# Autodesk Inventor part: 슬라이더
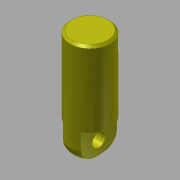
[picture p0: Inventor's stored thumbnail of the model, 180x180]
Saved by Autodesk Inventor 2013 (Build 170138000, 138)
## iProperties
Created: 2016-08
Part Number: 슬라이더
Material: 강철, 탄소
Document SubType Name: Modeling
Designer: mduedu
Density: 7.87 g/cm^3
Author: mduedu
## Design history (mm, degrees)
sketch "스케치1"
  geometry: C1 r 9 at (0, 0); 1 further point
  constraints: 1 centre point, 1 coincident
  dimensions: "d0" = 18 diameter of C1
extrude "돌출1" new body sketch "스케치1" distance "d1" = 47; taper "d2" = 0 deg
fillet "모깎기1" dims "d21" = 6
sketch "스케치6"
  geometry: L1 (9, 6)-(9, 47) reference; L2 (-9, 6)-(-9, 47) reference; L3 (9, 47)-(-9, 47) reference; L4 (0, 47)-(0, 0); L5 (9, 13)-(4, 13); L6 (4, 13)-(4, 0); L7 (4, 0)-(9, 0); L8 (9, 0)-(9, 13); L9 (-9, 13)-(-4, 13); L10 (-4, 13)-(-4, 0); L11 (-4, 0)-(-9, 0); L12 (-9, 0)-(-9, 13)
  constraints: 18 end point, 4 symmetric about line, 2 parallel, 2 perpendicular, 1 horizontal, 1 horizontal alignment, 1 midpoint, 1 point on line
  dimensions: "d22" = 13 distance of L7.end L5.start; "d24" = 4 distance between parallel lines of L6 L4
extrude "돌출5" cut sketch "스케치6" stored distance "d25" = 8; taper "d26" = 0 deg
sketch "스케치8"
  geometry: C1 r 3 at (6, 0); 1 further point
  constraints: 1 centre point, 1 horizontal alignment
  dimensions: "d27" = 6 diameter of C1; "d28" = 6 distance of point (0, 0) C1.centre
extrude "돌출6" cut sketch "스케치8" stored distance "d29" = 8; taper "d30" = 0 deg
chamfer "모따기2" distance "d43" = 1; stored, may be unused: second distance "d44" = 2, angle "d45" = 30 deg
node "솔리드1"
